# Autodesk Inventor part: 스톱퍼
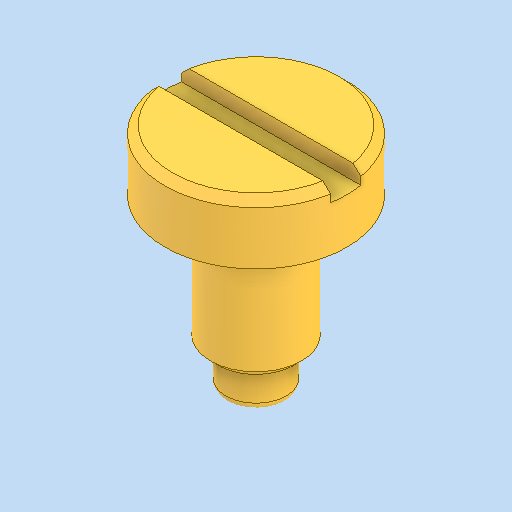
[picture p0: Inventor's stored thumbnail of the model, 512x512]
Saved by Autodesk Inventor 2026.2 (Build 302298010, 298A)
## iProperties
Created: 2026-08
Part Number: 스톱퍼
Material: 스테인리스강
Document SubType Name: Modeling
Designer: PC-2-06
Density: 8.08 g/cm^3
Appearance: 기본값
Author: jhkim
Sending System: Autodesk Inventor 2027
Preprocessor: ST-DEVELOPER v20.1
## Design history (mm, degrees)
feature "솔리드1"
node "솔리드2"
